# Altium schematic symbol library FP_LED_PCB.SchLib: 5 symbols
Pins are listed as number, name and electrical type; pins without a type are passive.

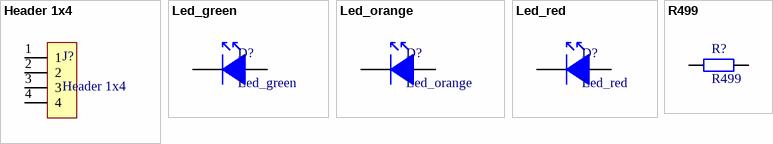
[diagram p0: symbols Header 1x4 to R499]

## Header 1x4
designator J?
footprint HDR4X1_FEMALE
pins: 1, 2, 3, 4

## Led_green
designator D?
1206
footprint led_green_10mm
pins: 1, 2

## Led_orange
designator D?
1206
footprint led_orange_10mm
pins: 1, 2

## Led_red
designator D?
1206
footprint led_red_10mm
pins: 1, 2

## R499
designator R?
footprint RES1206
pins: 1, 2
